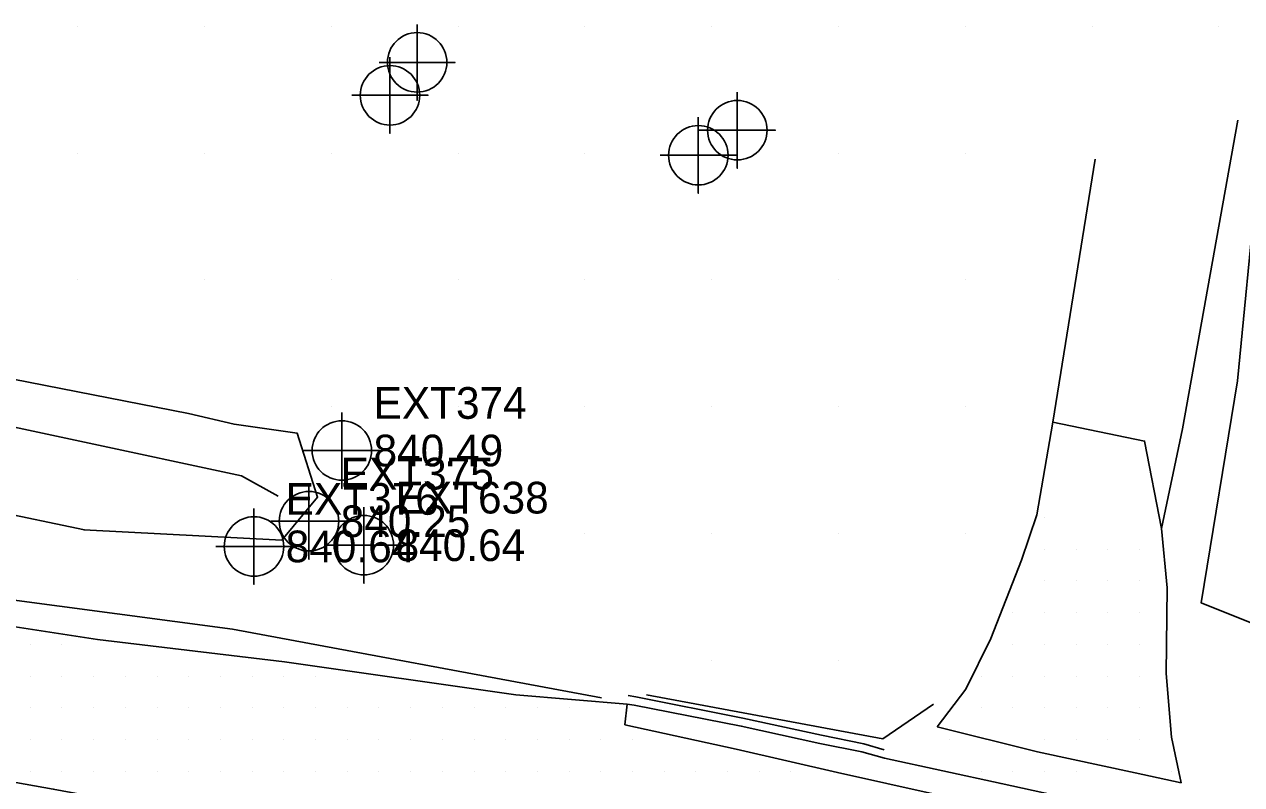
# Model space of a CAD drawing. Extents: x 1762120 to 1766775, y 709485 to 712965.
# Drawn here: x 1762995.8 to 1763091.8, y 712600.2 to 712660.1 of the extents above; entities that cross this region are included whole.
import ezdxf

# ---------------------------------------------------------------- set-up
doc = ezdxf.new("R2010")
doc.units = 0
for name, color, linetype in [('Exist DTM Breakline', 7, 'Continuous'), ('Exist DTM Breakline Cogo Elevation', 7, 'Continuous'), ('Exist DTM Breakline Cogo Number', 7, 'Continuous'), ('Exist DTM Breakline Cogo Point CELL', 7, 'Continuous'), ('Exist DTM Drainline', 7, 'Continuous'), ('Exist DTM QL2 LIDAR Elevation Point', 7, 'Continuous'), ('Exist DTM Regular Point CELL', 7, 'Continuous'), ('Exist DTM Regular Point Cogo Elevation', 7, 'Continuous'), ('Exist DTM Regular Point Cogo Number', 7, 'Continuous'), ('Exist DTM Scan Elevation Point', 7, 'Continuous'), ('Exist Roads Change in Surface', 7, 'Continuous'), ('Exist Roads Curbs', 7, 'Continuous'), ('Exist Roads EOP', 7, 'Continuous'), ('Exist Roads EOT', 7, 'Continuous'), ('Exist Roads Soil', 7, 'Continuous')]:
    doc.layers.add(name, color=color, linetype=linetype)

msp = doc.modelspace()

# ---------------------------------------------------------------- linework, layer by layer
at = {"layer": 'Exist DTM Breakline'}
for points in [[(1763187.482, 712586.62), (1763166.605, 712594.37), (1763153.077, 712594.951), (1763137.436, 712600.709), (1763106.659, 712607.304), (1763088.608, 712614.513), (1763091.465, 712632.035), (1763092.973, 712647.425)], [(1762978.658, 712624.861), (1763000.523, 712620.281), (1763000.478, 712620.273), (1763016.095, 712619.477), (1763018.914, 712622.867), (1763017.313, 712627.895), (1763012.329, 712628.602), (1763008.73, 712629.463), (1762982.253, 712634.642)], [(1763041.314, 712607.04), (1763012.197, 712612.435), (1762975.399, 712617.334)], [(1763067.497, 712606.532), (1763063.484, 712603.798), (1763044.864, 712607.275)]]:
    msp.add_lwpolyline(points, dxfattribs=at)
at = {"layer": 'Exist DTM Breakline Cogo Point CELL'}
for points in [[(1763020.828, 712629.536), (1763020.828, 712623.536), (1763020.828, 712626.536), (1763023.828, 712626.536), (1763017.828, 712626.536)], [(1763018.233, 712623.959), (1763018.233, 712617.959), (1763018.233, 712620.959), (1763021.233, 712620.959), (1763015.233, 712620.959)], [(1763013.897, 712621.97), (1763013.897, 712615.97), (1763013.897, 712618.97), (1763016.897, 712618.97), (1763010.897, 712618.97)]]:
    msp.add_lwpolyline(points, dxfattribs=at)
for centre in [(1763020.828, 712626.536), (1763018.233, 712620.959), (1763013.897, 712618.97)]:
    msp.add_circle(centre, 2.344, dxfattribs=at)
at = {"layer": 'Exist DTM Drainline'}
for points in [[(1763015.815, 712622.945), (1763012.902, 712624.529), (1762987.372, 712630.001), (1762981.958, 712630.554)], [(1763043.332, 712606.528), (1763043.869, 712606.449), (1763052.322, 712604.796), (1763058.532, 712603.432), (1763061.85, 712602.76), (1763063.615, 712602.275), (1763072.819, 712600.27), (1763080.163, 712598.678), (1763089.461, 712596.666)]]:
    msp.add_lwpolyline(points, dxfattribs=at)
at = {"layer": 'Exist DTM QL2 LIDAR Elevation Point'}
for p, q in [((1763000, 712660), (1763000, 712660)), ((1763010, 712660), (1763010, 712660)), ((1763020, 712660), (1763020, 712660)), ((1763030, 712660), (1763030, 712660)), ((1763040, 712660), (1763040, 712660)), ((1763050, 712660), (1763050, 712660)), ((1763060, 712660), (1763060, 712660)), ((1763070, 712660), (1763070, 712660)), ((1763080, 712660), (1763080, 712660)), ((1763090, 712660), (1763090, 712660)), ((1763000, 712650), (1763000, 712650)), ((1763010, 712650), (1763010, 712650)), ((1763020, 712650), (1763020, 712650)), ((1763030, 712650), (1763030, 712650)), ((1763040, 712650), (1763040, 712650)), ((1763060, 712650), (1763060, 712650)), ((1763070, 712650), (1763070, 712650)), ((1763000, 712640), (1763000, 712640)), ((1763010, 712640), (1763010, 712640)), ((1763020, 712640), (1763020, 712640)), ((1763030, 712640), (1763030, 712640)), ((1763040, 712640), (1763040, 712640)), ((1763050, 712640), (1763050, 712640)), ((1763060, 712640), (1763060, 712640)), ((1763070, 712640), (1763070, 712640)), ((1763020, 712630), (1763020, 712630)), ((1763030, 712630), (1763030, 712630)), ((1763040, 712630), (1763040, 712630)), ((1763050, 712630), (1763050, 712630)), ((1763060, 712630), (1763060, 712630)), ((1763070, 712630), (1763070, 712630)), ((1763030, 712620), (1763030, 712620)), ((1763040, 712620), (1763040, 712620)), ((1763050, 712620), (1763050, 712620)), ((1763060, 712620), (1763060, 712620)), ((1763070, 712620), (1763070, 712620)), ((1763050, 712610), (1763050, 712610)), ((1763060, 712610), (1763060, 712610))]:
    msp.add_line(p, q, dxfattribs=at)
at = {"layer": 'Exist DTM Regular Point CELL'}
for points in [[(1763026.763, 712660.148), (1763026.763, 712654.148), (1763026.763, 712657.148), (1763029.763, 712657.148), (1763023.763, 712657.148)], [(1763024.624, 712657.55), (1763024.624, 712651.55), (1763024.624, 712654.55), (1763027.624, 712654.55), (1763021.624, 712654.55)], [(1763052.018, 712654.798), (1763052.018, 712648.798), (1763052.018, 712651.798), (1763055.018, 712651.798), (1763049.018, 712651.798)], [(1763048.942, 712652.822), (1763048.942, 712646.822), (1763048.942, 712649.822), (1763051.942, 712649.822), (1763045.942, 712649.822)], [(1763022.561, 712622.068), (1763022.561, 712616.068), (1763022.561, 712619.068), (1763025.561, 712619.068), (1763019.561, 712619.068)]]:
    msp.add_lwpolyline(points, dxfattribs=at)
for centre in [(1763026.763, 712657.148), (1763024.624, 712654.55), (1763052.018, 712651.798), (1763048.942, 712649.822), (1763022.561, 712619.068)]:
    msp.add_circle(centre, 2.344, dxfattribs=at)
at = {"layer": 'Exist DTM Scan Elevation Point'}
for p, q in [((1763076.25, 712621.25), (1763076.25, 712621.25)), ((1763076.25, 712618.75), (1763076.25, 712618.75)), ((1763078.75, 712618.75), (1763078.75, 712618.75)), ((1763081.25, 712618.75), (1763081.25, 712618.75)), ((1763083.75, 712618.75), (1763083.75, 712618.75)), ((1763076.25, 712616.25), (1763076.25, 712616.25)), ((1763078.75, 712616.25), (1763078.75, 712616.25)), ((1763081.25, 712616.25), (1763081.25, 712616.25)), ((1763083.75, 712616.25), (1763083.75, 712616.25)), ((1763073.75, 712613.75), (1763073.75, 712613.75)), ((1763076.25, 712613.75), (1763076.25, 712613.75)), ((1763078.75, 712613.75), (1763078.75, 712613.75)), ((1763081.25, 712613.75), (1763081.25, 712613.75)), ((1763083.75, 712613.75), (1763083.75, 712613.75)), ((1762996.25, 712611.25), (1762996.25, 712611.25)), ((1762998.75, 712611.25), (1762998.75, 712611.25)), ((1763073.75, 712611.25), (1763073.75, 712611.25)), ((1763076.25, 712611.25), (1763076.25, 712611.25)), ((1763078.75, 712611.25), (1763078.75, 712611.25)), ((1763081.25, 712611.25), (1763081.25, 712611.25)), ((1763083.75, 712611.25), (1763083.75, 712611.25)), ((1762996.25, 712608.75), (1762996.25, 712608.75)), ((1762998.75, 712608.75), (1762998.75, 712608.75)), ((1763001.25, 712608.75), (1763001.25, 712608.75)), ((1763003.75, 712608.75), (1763003.75, 712608.75)), ((1763006.25, 712608.75), (1763006.25, 712608.75)), ((1763008.75, 712608.75), (1763008.75, 712608.75)), ((1763011.25, 712608.75), (1763011.25, 712608.75)), ((1763013.75, 712608.75), (1763013.75, 712608.75)), ((1763016.25, 712608.75), (1763016.25, 712608.75)), ((1763018.75, 712608.75), (1763018.75, 712608.75)), ((1763071.25, 712608.75), (1763071.25, 712608.75)), ((1763073.75, 712608.75), (1763073.75, 712608.75)), ((1763076.25, 712608.75), (1763076.25, 712608.75)), ((1763078.75, 712608.75), (1763078.75, 712608.75)), ((1763081.25, 712608.75), (1763081.25, 712608.75)), ((1763083.75, 712608.75), (1763083.75, 712608.75)), ((1762996.25, 712606.25), (1762996.25, 712606.25)), ((1762998.75, 712606.25), (1762998.75, 712606.25)), ((1763001.25, 712606.25), (1763001.25, 712606.25)), ((1763003.75, 712606.25), (1763003.75, 712606.25)), ((1763006.25, 712606.25), (1763006.25, 712606.25)), ((1763008.75, 712606.25), (1763008.75, 712606.25)), ((1763011.25, 712606.25), (1763011.25, 712606.25)), ((1763013.75, 712606.25), (1763013.75, 712606.25)), ((1763016.25, 712606.25), (1763016.25, 712606.25)), ((1763018.75, 712606.25), (1763018.75, 712606.25)), ((1763021.25, 712606.25), (1763021.25, 712606.25)), ((1763023.75, 712606.25), (1763023.75, 712606.25)), ((1763026.25, 712606.25), (1763026.25, 712606.25)), ((1763028.75, 712606.25), (1763028.75, 712606.25)), ((1763031.25, 712606.25), (1763031.25, 712606.25)), ((1763033.75, 712606.25), (1763033.75, 712606.25)), ((1763036.25, 712606.25), (1763036.25, 712606.25)), ((1763038.75, 712606.25), (1763038.75, 712606.25)), ((1763071.25, 712606.25), (1763071.25, 712606.25)), ((1763073.75, 712606.25), (1763073.75, 712606.25)), ((1763076.25, 712606.25), (1763076.25, 712606.25)), ((1763078.75, 712606.25), (1763078.75, 712606.25)), ((1763081.25, 712606.25), (1763081.25, 712606.25)), ((1763083.75, 712606.25), (1763083.75, 712606.25)), ((1762996.25, 712603.75), (1762996.25, 712603.75)), ((1762998.75, 712603.75), (1762998.75, 712603.75)), ((1763001.25, 712603.75), (1763001.25, 712603.75)), ((1763003.75, 712603.75), (1763003.75, 712603.75)), ((1763006.25, 712603.75), (1763006.25, 712603.75)), ((1763008.75, 712603.75), (1763008.75, 712603.75)), ((1763011.25, 712603.75), (1763011.25, 712603.75)), ((1763013.75, 712603.75), (1763013.75, 712603.75)), ((1763016.25, 712603.75), (1763016.25, 712603.75)), ((1763018.75, 712603.75), (1763018.75, 712603.75)), ((1763021.25, 712603.75), (1763021.25, 712603.75)), ((1763023.75, 712603.75), (1763023.75, 712603.75)), ((1763026.25, 712603.75), (1763026.25, 712603.75)), ((1763028.75, 712603.75), (1763028.75, 712603.75)), ((1763031.25, 712603.75), (1763031.25, 712603.75)), ((1763033.75, 712603.75), (1763033.75, 712603.75)), ((1763036.25, 712603.75), (1763036.25, 712603.75)), ((1763038.75, 712603.75), (1763038.75, 712603.75)), ((1763041.25, 712603.75), (1763041.25, 712603.75)), ((1763043.75, 712603.75), (1763043.75, 712603.75)), ((1763068.75, 712603.75), (1763068.75, 712603.75)), ((1763076.25, 712603.75), (1763076.25, 712603.75)), ((1763078.75, 712603.75), (1763078.75, 712603.75)), ((1763081.25, 712603.75), (1763081.25, 712603.75)), ((1763083.75, 712603.75), (1763083.75, 712603.75)), ((1762996.25, 712601.25), (1762996.25, 712601.25)), ((1762998.75, 712601.25), (1762998.75, 712601.25)), ((1763001.25, 712601.25), (1763001.25, 712601.25)), ((1763003.75, 712601.25), (1763003.75, 712601.25)), ((1763006.25, 712601.25), (1763006.25, 712601.25)), ((1763008.75, 712601.25), (1763008.75, 712601.25)), ((1763011.25, 712601.25), (1763011.25, 712601.25)), ((1763013.75, 712601.25), (1763013.75, 712601.25)), ((1763016.25, 712601.25), (1763016.25, 712601.25)), ((1763018.75, 712601.25), (1763018.75, 712601.25)), ((1763021.25, 712601.25), (1763021.25, 712601.25)), ((1763023.75, 712601.25), (1763023.75, 712601.25)), ((1763026.25, 712601.25), (1763026.25, 712601.25)), ((1763028.75, 712601.25), (1763028.75, 712601.25)), ((1763031.25, 712601.25), (1763031.25, 712601.25)), ((1763033.75, 712601.25), (1763033.75, 712601.25)), ((1763036.25, 712601.25), (1763036.25, 712601.25)), ((1763038.75, 712601.25), (1763038.75, 712601.25)), ((1763041.25, 712601.25), (1763041.25, 712601.25)), ((1763043.75, 712601.25), (1763043.75, 712601.25)), ((1763046.25, 712601.25), (1763046.25, 712601.25)), ((1763048.75, 712601.25), (1763048.75, 712601.25)), ((1763051.25, 712601.25), (1763051.25, 712601.25)), ((1763053.75, 712601.25), (1763053.75, 712601.25)), ((1763056.25, 712601.25), (1763056.25, 712601.25)), ((1763071.25, 712601.25), (1763071.25, 712601.25)), ((1763073.75, 712601.25), (1763073.75, 712601.25)), ((1763076.25, 712601.25), (1763076.25, 712601.25)), ((1763078.75, 712601.25), (1763078.75, 712601.25)), ((1763086.25, 712601.25), (1763086.25, 712601.25))]:
    msp.add_line(p, q, dxfattribs=at)
at = {"layer": 'Exist Roads Change in Surface'}
msp.add_lwpolyline([(1763067.785, 712604.753), (1763075.683, 712602.774), (1763083.393, 712601.107), (1763087.011, 712600.318)], dxfattribs=at)
at = {"layer": 'Exist Roads Curbs'}
msp.add_lwpolyline([(1763043.416, 712607.218), (1763044.007, 712607.119), (1763052.458, 712605.42), (1763058.665, 712604.074), (1763062, 712603.4), (1763063.596, 712602.938)], dxfattribs=at)
at = {"layer": 'Exist Roads EOP'}
msp.add_line((1763043.332, 712606.528), (1763043.134, 712604.895), dxfattribs=at)
for points in [[(1763067.785, 712604.753), (1763070.042, 712607.706), (1763072.004, 712611.699), (1763074.429, 712617.892), (1763075.636, 712621.467), (1763076.896, 712628.766), (1763084.141, 712627.277), (1763085.471, 712620.381)], [(1763087.011, 712600.318), (1763086.257, 712603.939), (1763085.828, 712608.939), (1763085.924, 712615.699), (1763085.471, 712620.381)], [(1762972.643, 712616.327), (1762987.52, 712613.78), (1763001.56, 712611.62), (1763016.31, 712609.88), (1763034.56, 712607.27), (1763043.332, 712606.528)], [(1763043.134, 712604.895), (1763051.924, 712602.974), (1763059.92, 712601.15)], [(1763059.92, 712601.15), (1763075.24, 712597.71), (1763090.11, 712594.46)]]:
    msp.add_lwpolyline(points, dxfattribs=at)
at = {"layer": 'Exist Roads EOT'}
msp.add_lwpolyline([(1762970.656, 712604.722), (1762998.06, 712599.827), (1763022.414, 712595.32), (1763039.9, 712592.003), (1763056.38, 712588.88)], dxfattribs=at)
at = {"layer": 'Exist Roads Soil'}
for points in [[(1763091.502, 712652.595), (1763087.118, 712628.234), (1763085.471, 712620.381)], [(1763076.896, 712628.766), (1763080.235, 712649.527)]]:
    msp.add_lwpolyline(points, dxfattribs=at)

# ---------------------------------------------------------------- texts
at = {"layer": 'Exist DTM Breakline Cogo Elevation'}
for s, p in [('840.49', (1763023.328, 712625.286)), ('840.25', (1763020.733, 712619.709)), ('840.64', (1763016.397, 712617.72))]:
    msp.add_text(s, height=2.5, dxfattribs=at).set_placement(p)
at = {"layer": 'Exist DTM Breakline Cogo Number'}
for s, p in [('EXT374', (1763023.328, 712629.036)), ('EXT375', (1763020.733, 712623.459)), ('EXT376', (1763016.397, 712621.47))]:
    msp.add_text(s, height=2.5, dxfattribs=at).set_placement(p)
at = {"layer": 'Exist DTM Regular Point Cogo Elevation'}
msp.add_text('840.64', height=2.5, dxfattribs=at).set_placement((1763025.061, 712617.818))
at = {"layer": 'Exist DTM Regular Point Cogo Number'}
msp.add_text('EXT638', height=2.5, dxfattribs=at).set_placement((1763025.061, 712621.568))

doc.saveas('drawing.dxf')
